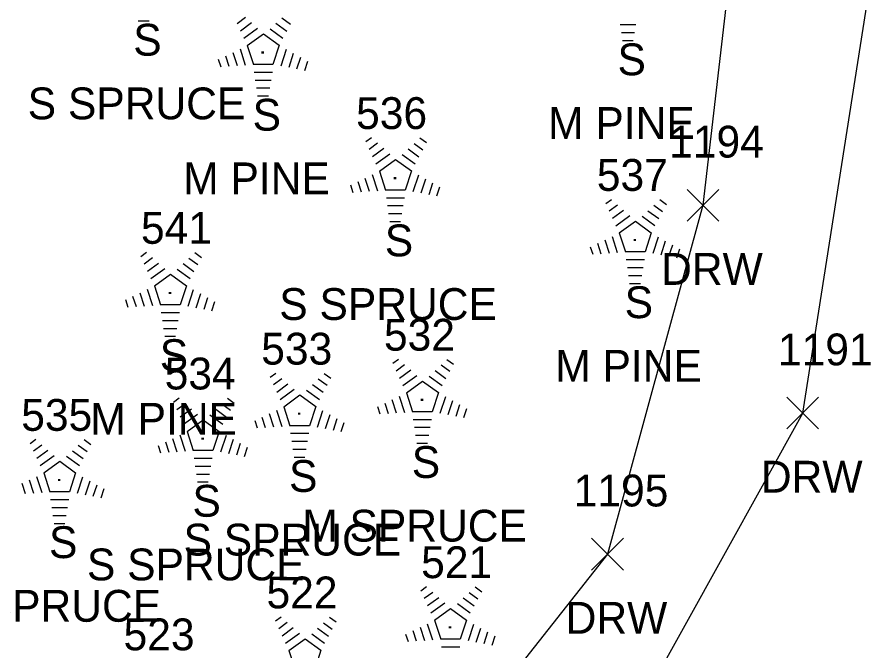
# Model space of a CAD drawing. Extents: x 1545627 to 1546562, y 571176 to 576667.
# Drawn here: x 1546247.4 to 1546301.3, y 571891 to 571930.9 of the extents above; entities that cross this region are included whole.
import ezdxf

# ---------------------------------------------------------------- set-up
doc = ezdxf.new("R2010")
doc.units = 0
for name, color, linetype in [('L_A', 7, 'Continuous'), ('L_C', 7, 'Continuous'), ('L_I', 7, 'Continuous'), ('LTC', 7, 'Continuous'), ('R_A', 7, 'Continuous'), ('R_I', 7, 'Continuous'), ('R_TIC', 7, 'Continuous'), ('RDW', 7, 'Continuous')]:
    doc.layers.add(name, color=color, linetype=linetype)

msp = doc.modelspace()

# ---------------------------------------------------------------- linework, layer by layer
at = {"layer": 'LTC'}
for p, q in [((1546255.733, 571930.607), (1546255.058, 571930.607)), ((1546261.262, 571930.474), (1546261.791, 571930.858)), ((1546261.472, 571930.008), (1546262.175, 571930.52)), ((1546263.709, 571930.483), (1546264.388, 571929.99)), ((1546264.079, 571930.832), (1546264.629, 571930.432)), ((1546286.328, 571930.376), (1546285.339, 571930.376)), ((1546261.681, 571929.542), (1546262.559, 571930.18)), ((1546263.337, 571930.135), (1546264.147, 571929.546)), ((1546286.244, 571929.876), (1546285.412, 571929.876)), ((1546261.906, 571929.087), (1546262.917, 571929.822)), ((1546262.917, 571929.822), (1546263.914, 571929.097)), ((1546286.16, 571929.376), (1546285.485, 571929.376)), ((1546261.451, 571928.868), (1546261.782, 571927.849)), ((1546261.906, 571929.087), (1546262.293, 571927.894)), ((1546263.914, 571929.097), (1546263.523, 571927.894)), ((1546264.352, 571928.826), (1546264.014, 571927.787)), ((1546260.085, 571928.219), (1546260.237, 571927.751)), ((1546260.54, 571928.435), (1546260.752, 571927.784)), ((1546260.996, 571928.652), (1546261.267, 571927.817)), ((1546264.797, 571928.576), (1546264.509, 571927.691)), ((1546265.241, 571928.326), (1546265.004, 571927.596)), ((1546263.523, 571927.894), (1546262.293, 571927.894)), ((1546265.685, 571928.075), (1546265.499, 571927.501)), ((1546263.485, 571927.394), (1546262.34, 571927.394)), ((1546263.401, 571926.894), (1546262.413, 571926.894)), ((1546263.317, 571926.394), (1546262.486, 571926.394)), ((1546263.234, 571925.894), (1546262.559, 571925.894)), ((1546269.356, 571923.041), (1546269.71, 571923.299)), ((1546269.565, 571922.576), (1546270.095, 571922.96)), ((1546272.383, 571922.933), (1546272.933, 571922.534)), ((1546272.754, 571923.282), (1546273.173, 571922.977)), ((1546269.775, 571922.11), (1546270.479, 571922.621)), ((1546272.012, 571922.585), (1546272.691, 571922.091)), ((1546269.985, 571921.644), (1546270.863, 571922.282)), ((1546270.209, 571921.189), (1546271.221, 571921.924)), ((1546271.221, 571921.924), (1546272.218, 571921.199)), ((1546271.641, 571922.237), (1546272.45, 571921.648)), ((1546269.299, 571920.754), (1546269.57, 571919.918)), ((1546269.755, 571920.97), (1546270.085, 571919.951)), ((1546270.209, 571921.189), (1546270.596, 571919.996)), ((1546272.218, 571921.199), (1546271.827, 571919.996)), ((1546272.655, 571920.928), (1546272.318, 571919.888)), ((1546268.388, 571920.321), (1546268.54, 571919.853)), ((1546268.844, 571920.537), (1546269.055, 571919.886)), ((1546273.1, 571920.678), (1546272.813, 571919.793)), ((1546273.545, 571920.428), (1546273.308, 571919.698)), ((1546273.989, 571920.177), (1546273.802, 571919.603)), ((1546271.827, 571919.996), (1546270.596, 571919.996)), ((1546271.788, 571919.496), (1546270.644, 571919.496)), ((1546284.425, 571919.155), (1546284.78, 571919.412)), ((1546284.635, 571918.689), (1546285.164, 571919.074)), ((1546287.824, 571919.395), (1546288.243, 571919.091)), ((1546271.705, 571918.996), (1546270.716, 571918.996)), ((1546284.844, 571918.224), (1546285.548, 571918.735)), ((1546287.081, 571918.699), (1546287.761, 571918.205)), ((1546287.452, 571919.047), (1546288.002, 571918.648)), ((1546271.621, 571918.496), (1546270.789, 571918.496)), ((1546271.537, 571917.996), (1546270.862, 571917.996)), ((1546285.054, 571917.758), (1546285.932, 571918.396)), ((1546285.279, 571917.303), (1546286.29, 571918.037)), ((1546286.29, 571918.037), (1546287.287, 571917.312)), ((1546286.71, 571918.35), (1546287.52, 571917.761)), ((1546284.824, 571917.084), (1546285.155, 571916.064)), ((1546285.279, 571917.303), (1546285.666, 571916.109)), ((1546287.287, 571917.312), (1546286.896, 571916.109)), ((1546287.725, 571917.041), (1546287.387, 571916.002)), ((1546283.458, 571916.434), (1546283.61, 571915.966)), ((1546283.913, 571916.651), (1546284.125, 571915.999)), ((1546284.369, 571916.867), (1546284.64, 571916.032)), ((1546288.169, 571916.791), (1546287.882, 571915.906)), ((1546288.614, 571916.541), (1546288.377, 571915.811)), ((1546255.217, 571915.83), (1546255.572, 571916.087)), ((1546258.616, 571916.07), (1546259.035, 571915.765)), ((1546286.896, 571916.109), (1546285.666, 571916.109)), ((1546289.058, 571916.291), (1546288.871, 571915.716)), ((1546255.427, 571915.364), (1546255.956, 571915.748)), ((1546255.637, 571914.898), (1546256.34, 571915.41)), ((1546257.874, 571915.373), (1546258.553, 571914.88)), ((1546258.244, 571915.722), (1546258.794, 571915.322)), ((1546286.858, 571915.609), (1546285.713, 571915.609)), ((1546255.846, 571914.432), (1546256.724, 571915.07)), ((1546257.502, 571915.025), (1546258.312, 571914.436)), ((1546286.774, 571915.109), (1546285.786, 571915.109)), ((1546256.071, 571913.977), (1546257.082, 571914.712)), ((1546257.082, 571914.712), (1546258.079, 571913.987)), ((1546286.69, 571914.609), (1546285.859, 571914.609)), ((1546255.616, 571913.758), (1546255.947, 571912.739)), ((1546256.071, 571913.977), (1546256.458, 571912.784)), ((1546258.079, 571913.987), (1546257.688, 571912.784)), ((1546258.517, 571913.716), (1546258.179, 571912.677)), ((1546286.606, 571914.109), (1546285.931, 571914.109)), ((1546254.705, 571913.325), (1546254.917, 571912.674)), ((1546255.161, 571913.542), (1546255.432, 571912.707)), ((1546258.962, 571913.466), (1546258.674, 571912.581)), ((1546259.406, 571913.216), (1546259.169, 571912.486)), ((1546254.25, 571913.109), (1546254.402, 571912.641)), ((1546257.688, 571912.784), (1546256.458, 571912.784)), ((1546259.85, 571912.965), (1546259.664, 571912.391)), ((1546257.65, 571912.284), (1546256.505, 571912.284)), ((1546257.566, 571911.784), (1546256.578, 571911.784)), ((1546257.482, 571911.284), (1546256.651, 571911.284)), ((1546257.399, 571910.784), (1546256.724, 571910.784)), ((1546271.052, 571909.111), (1546271.406, 571909.368)), ((1546271.261, 571908.645), (1546271.79, 571909.029)), ((1546274.079, 571909.003), (1546274.628, 571908.604)), ((1546274.45, 571909.351), (1546274.869, 571909.046)), ((1546263.342, 571908.234), (1546263.696, 571908.491)), ((1546266.74, 571908.474), (1546267.159, 571908.17)), ((1546271.471, 571908.179), (1546272.174, 571908.691)), ((1546271.68, 571907.714), (1546272.559, 571908.351)), ((1546273.337, 571908.306), (1546274.146, 571907.717)), ((1546273.708, 571908.654), (1546274.387, 571908.161)), ((1546263.551, 571907.768), (1546264.081, 571908.153)), ((1546263.761, 571907.303), (1546264.465, 571907.814)), ((1546265.998, 571907.778), (1546266.677, 571907.284)), ((1546266.369, 571908.126), (1546266.919, 571907.727)), ((1546271.905, 571907.259), (1546272.917, 571907.993)), ((1546272.917, 571907.993), (1546273.914, 571907.268)), ((1546263.971, 571906.837), (1546264.849, 571907.475)), ((1546265.627, 571907.429), (1546266.436, 571906.841)), ((1546271.905, 571907.259), (1546272.292, 571906.065)), ((1546273.914, 571907.268), (1546273.522, 571906.065)), ((1546257.273, 571906.673), (1546257.628, 571906.93)), ((1546260.672, 571906.913), (1546261.091, 571906.609)), ((1546264.195, 571906.382), (1546265.207, 571907.116)), ((1546265.207, 571907.116), (1546266.204, 571906.391)), ((1546270.995, 571906.823), (1546271.266, 571905.988)), ((1546271.45, 571907.039), (1546271.781, 571906.02)), ((1546274.351, 571906.997), (1546274.013, 571905.958)), ((1546274.796, 571906.747), (1546274.508, 571905.862)), ((1546257.483, 571906.208), (1546258.012, 571906.592)), ((1546257.693, 571905.742), (1546258.396, 571906.253)), ((1546259.93, 571906.217), (1546260.609, 571905.723)), ((1546260.301, 571906.565), (1546260.85, 571906.166)), ((1546263.741, 571906.163), (1546264.071, 571905.143)), ((1546264.195, 571906.382), (1546264.582, 571905.188)), ((1546266.204, 571906.391), (1546265.813, 571905.188)), ((1546270.084, 571906.39), (1546270.236, 571905.922)), ((1546270.539, 571906.606), (1546270.751, 571905.955)), ((1546275.24, 571906.497), (1546275.003, 571905.767)), ((1546275.684, 571906.246), (1546275.498, 571905.672)), ((1546257.902, 571905.276), (1546258.781, 571905.914)), ((1546259.558, 571905.868), (1546260.368, 571905.28)), ((1546262.83, 571905.73), (1546263.041, 571905.078)), ((1546263.285, 571905.946), (1546263.556, 571905.111)), ((1546266.641, 571906.121), (1546266.304, 571905.081)), ((1546267.086, 571905.87), (1546266.799, 571904.986)), ((1546267.531, 571905.62), (1546267.294, 571904.891)), ((1546273.522, 571906.065), (1546272.292, 571906.065)), ((1546258.127, 571904.821), (1546259.138, 571905.556)), ((1546259.138, 571905.556), (1546260.136, 571904.831)), ((1546262.374, 571905.513), (1546262.526, 571905.045)), ((1546265.813, 571905.188), (1546264.582, 571905.188)), ((1546267.975, 571905.37), (1546267.788, 571904.796)), ((1546273.484, 571905.565), (1546272.339, 571905.565)), ((1546257.672, 571904.602), (1546258.003, 571903.583)), ((1546258.127, 571904.821), (1546258.514, 571903.628)), ((1546260.136, 571904.831), (1546259.744, 571903.628)), ((1546260.573, 571904.56), (1546260.235, 571903.52)), ((1546265.774, 571904.688), (1546264.63, 571904.688)), ((1546273.4, 571905.065), (1546272.412, 571905.065)), ((1546273.317, 571904.565), (1546272.485, 571904.565)), ((1546248.262, 571904.073), (1546248.617, 571904.331)), ((1546251.661, 571904.313), (1546252.08, 571904.009)), ((1546256.761, 571904.169), (1546256.973, 571903.517)), ((1546257.217, 571904.386), (1546257.488, 571903.55)), ((1546261.018, 571904.309), (1546260.73, 571903.425)), ((1546261.462, 571904.059), (1546261.225, 571903.33)), ((1546265.691, 571904.188), (1546264.702, 571904.188)), ((1546273.233, 571904.065), (1546272.558, 571904.065)), ((1546248.472, 571903.608), (1546249.001, 571903.992)), ((1546248.681, 571903.142), (1546249.385, 571903.653)), ((1546250.918, 571903.617), (1546251.598, 571903.123)), ((1546251.289, 571903.965), (1546251.839, 571903.566)), ((1546256.306, 571903.952), (1546256.458, 571903.484)), ((1546259.744, 571903.628), (1546258.514, 571903.628)), ((1546261.906, 571903.809), (1546261.72, 571903.235)), ((1546265.607, 571903.688), (1546264.775, 571903.688)), ((1546248.891, 571902.676), (1546249.769, 571903.314)), ((1546249.116, 571902.221), (1546250.127, 571902.956)), ((1546250.127, 571902.956), (1546251.124, 571902.231)), ((1546250.547, 571903.268), (1546251.357, 571902.68)), ((1546259.706, 571903.128), (1546258.561, 571903.128)), ((1546265.523, 571903.188), (1546264.848, 571903.188)), ((1546259.622, 571902.628), (1546258.634, 571902.628)), ((1546248.661, 571902.002), (1546248.992, 571900.983)), ((1546249.116, 571902.221), (1546249.503, 571901.028)), ((1546251.124, 571902.231), (1546250.733, 571901.028)), ((1546251.562, 571901.96), (1546251.224, 571900.92)), ((1546259.538, 571902.128), (1546258.707, 571902.128)), ((1546247.75, 571901.569), (1546247.962, 571900.917)), ((1546248.206, 571901.786), (1546248.477, 571900.95)), ((1546252.006, 571901.709), (1546251.719, 571900.825)), ((1546252.451, 571901.459), (1546252.214, 571900.73)), ((1546259.455, 571901.628), (1546258.78, 571901.628)), ((1546250.733, 571901.028), (1546249.503, 571901.028)), ((1546252.895, 571901.209), (1546252.708, 571900.635)), ((1546250.695, 571900.528), (1546249.55, 571900.528)), ((1546250.611, 571900.028), (1546249.623, 571900.028)), ((1546250.527, 571899.528), (1546249.696, 571899.528)), ((1546250.443, 571899.028), (1546249.768, 571899.028)), ((1546272.82, 571894.813), (1546273.175, 571895.071)), ((1546276.219, 571895.054), (1546276.638, 571894.749)), ((1546273.03, 571894.348), (1546273.559, 571894.732)), ((1546273.239, 571893.882), (1546273.943, 571894.393)), ((1546275.476, 571894.357), (1546276.156, 571893.863)), ((1546275.847, 571894.705), (1546276.397, 571894.306)), ((1546273.449, 571893.416), (1546274.327, 571894.054)), ((1546275.105, 571894.009), (1546275.915, 571893.42)), ((1546273.674, 571892.961), (1546274.685, 571893.696)), ((1546274.685, 571893.696), (1546275.682, 571892.971)), ((1546263.672, 571892.913), (1546264.026, 571893.171)), ((1546263.881, 571892.448), (1546264.41, 571892.832)), ((1546266.699, 571892.805), (1546267.248, 571892.406)), ((1546267.07, 571893.154), (1546267.489, 571892.849)), ((1546273.219, 571892.742), (1546273.55, 571891.723)), ((1546273.674, 571892.961), (1546274.061, 571891.768)), ((1546275.682, 571892.971), (1546275.291, 571891.768)), ((1546276.12, 571892.7), (1546275.782, 571891.66)), ((1546264.091, 571891.982), (1546264.794, 571892.493)), ((1546264.3, 571891.516), (1546265.179, 571892.154)), ((1546266.328, 571892.457), (1546267.007, 571891.963)), ((1546272.308, 571892.309), (1546272.52, 571891.657)), ((1546272.764, 571892.526), (1546273.035, 571891.69)), ((1546276.564, 571892.449), (1546276.277, 571891.565)), ((1546277.009, 571892.199), (1546276.772, 571891.47)), ((1546264.525, 571891.061), (1546265.537, 571891.796)), ((1546265.537, 571891.796), (1546266.534, 571891.071)), ((1546265.957, 571892.109), (1546266.766, 571891.52)), ((1546271.853, 571892.092), (1546272.005, 571891.624)), ((1546275.291, 571891.768), (1546274.061, 571891.768)), ((1546277.453, 571891.949), (1546277.266, 571891.375)), ((1546275.253, 571891.268), (1546274.108, 571891.268)), ((1546264.525, 571891.061), (1546264.912, 571889.868)), ((1546266.534, 571891.071), (1546266.142, 571889.868))]:
    msp.add_line(p, q, dxfattribs=at)
at = {"layer": 'R_TIC'}
for points in [[(1546289.538, 571918.039), (1546291.538, 571920.039)], [(1546291.538, 571918.039), (1546289.538, 571920.039)], [(1546295.805, 571904.979), (1546297.805, 571906.979)], [(1546297.805, 571904.979), (1546295.805, 571906.979)], [(1546283.539, 571896.111), (1546285.539, 571898.111)], [(1546285.539, 571896.111), (1546283.539, 571898.111)]]:
    msp.add_lwpolyline(points, dxfattribs=at)
at = {"layer": 'RDW'}
for points in [[(1546294.555, 571953.756), (1546290.538, 571919.039), (1546284.539, 571897.111), (1546266.736, 571874.517), (1546245.666, 571860.03), (1546228.586, 571855.541), (1546223.567, 571853.749), (1546218.613, 571853), (1546210.358, 571854.991), (1546208.219, 571856.105), (1546205.182, 571857.755)], [(1546213.044, 571834.88), (1546214.931, 571836.379), (1546217.305, 571838.705), (1546220.817, 571841.735), (1546225.642, 571844.556), (1546244.499, 571850.597), (1546263.872, 571861.801), (1546282.026, 571879.334), (1546296.805, 571905.979), (1546303.893, 571951.142)]]:
    msp.add_lwpolyline(points, dxfattribs=at)

# ---------------------------------------------------------------- texts
at = {"layer": 'L_A'}
for p in [(1546254.743, 571928.444), (1546285.17, 571927.213), (1546262.243, 571923.731), (1546270.547, 571915.833), (1546285.616, 571911.947), (1546256.408, 571908.621), (1546272.242, 571901.902), (1546264.533, 571901.026), (1546258.464, 571899.465), (1546249.453, 571896.865)]:
    msp.add_text('S', height=2, dxfattribs=at).set_placement(p)
at = {"layer": 'L_C'}
for s, p in [('S SPRUCE', (1546248.113, 571924.444)), ('M PINE', (1546280.807, 571923.213)), ('M PINE', (1546257.881, 571919.731)), ('S SPRUCE', (1546263.917, 571911.833)), ('M PINE', (1546281.254, 571907.947)), ('M PINE', (1546252.046, 571904.621)), ('M SPRUCE', (1546265.36, 571897.902)), ('S SPRUCE', (1546257.903, 571897.026)), ('S SPRUCE', (1546251.834, 571895.465)), ('S SPRUCE', (1546242.823, 571892.865))]:
    msp.add_text(s, height=2, dxfattribs=at).set_placement(p)
at = {"layer": 'L_I'}
for s, p in [('536', (1546268.743, 571923.833)), ('537', (1546283.868, 571919.947)), ('541', (1546255.227, 571916.621)), ('532', (1546270.494, 571909.902)), ('533', (1546262.784, 571909.026)), ('534', (1546256.716, 571907.465)), ('535', (1546247.705, 571904.865)), ('521', (1546272.83, 571895.605)), ('522', (1546263.114, 571893.705)), ('523', (1546254.134, 571891.07))]:
    msp.add_text(s, height=2, dxfattribs=at).set_placement(p)
at = {"layer": 'LTC'}
for p in [(1546262.8, 571928.835), (1546271.103, 571920.937), (1546286.173, 571917.051), (1546256.965, 571913.725), (1546272.799, 571907.006), (1546265.089, 571906.13), (1546259.021, 571904.569), (1546250.01, 571901.969), (1546274.568, 571892.709)]:
    msp.add_text('.', height=1.037, rotation=270, dxfattribs=at).set_placement(p)
at = {"layer": 'R_A'}
for p in [(1546287.908, 571914.039), (1546294.175, 571900.979), (1546281.909, 571892.111)]:
    msp.add_text('DRW', height=2, dxfattribs=at).set_placement(p)
at = {"layer": 'R_I'}
for s, p in [('1194', (1546288.412, 571922.039)), ('1191', (1546295.246, 571908.979)), ('1195', (1546282.413, 571900.111))]:
    msp.add_text(s, height=2, dxfattribs=at).set_placement(p)

doc.saveas('drawing.dxf')
